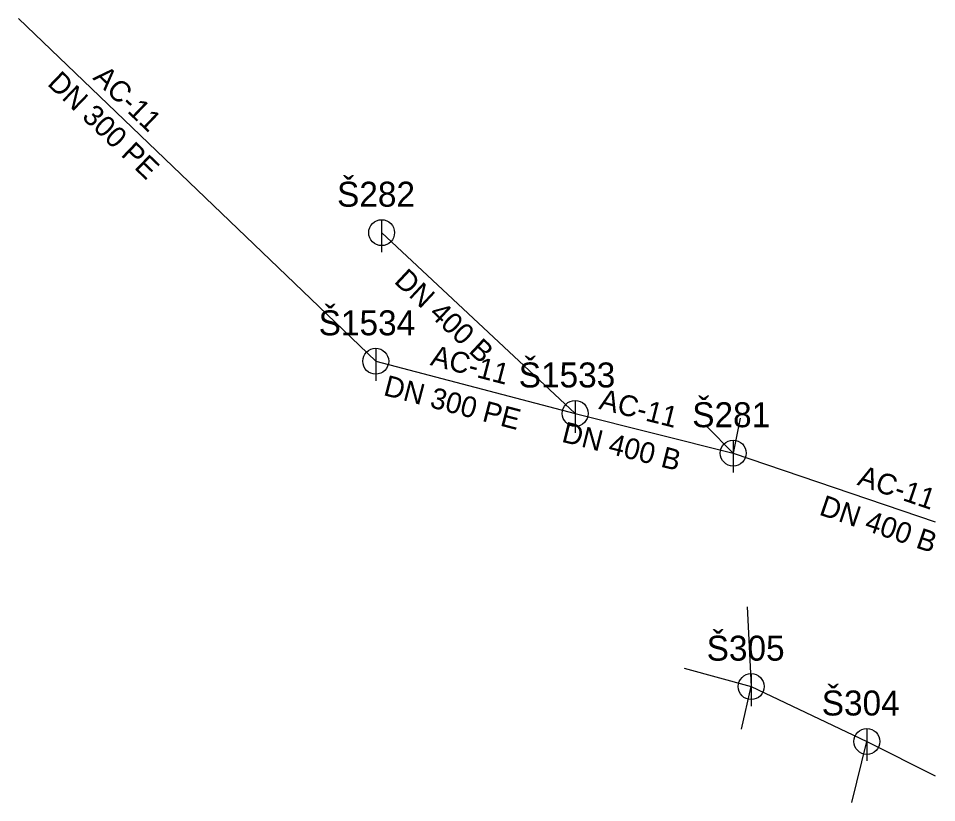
# Model space of a CAD drawing. Extents: x -483170.7 to -483099.9, y -1125989.9 to -1125929.4.
import ezdxf

# ---------------------------------------------------------------- set-up
doc = ezdxf.new("R2010")
doc.units = 0
for name, color, linetype in [('_pripojka_kanal_jednotna_priblizne_', 7, 'Continuous'), ('_stoka_destova_smvak_priblizne_', 7, 'Continuous'), ('_stoka_jednotna_provozovana_prevzato_z_dokumentace_', 7, 'Continuous'), ('_stoka_jednotna_smvak_prevzato_z_dokumentace_', 7, 'Continuous'), ('_stoka_jednotna_smvak_priblizne_', 7, 'Continuous'), ('Default', 7, 'Continuous'), ('MoLevel 1', 7, 'Continuous'), ('MoLevel 119', 7, 'Continuous'), ('MoLevel 120', 7, 'Continuous'), ('MoLevel 2', 7, 'Continuous'), ('MoLevel 5', 7, 'Continuous'), ('MoLevel 68', 7, 'Continuous'), ('MoLevel 69', 7, 'Continuous'), ('MoLevel 76', 7, 'Continuous'), ('MoLevel 77', 7, 'Continuous')]:
    doc.layers.add(name, color=color, linetype=linetype)

# ---------------------------------------------------------------- blocks, each defined once
blk = doc.blocks.new('_sachta_kanal_prevzato_z_dokumentace_')
at = {"layer": 'Default'}
blk.add_line((0, 0.00005), (0, -0.000075), dxfattribs=at)
blk.add_circle((0, 0), 0.00005, dxfattribs=at)

msp = doc.modelspace()

# ---------------------------------------------------------------- linework, layer by layer
at = {"layer": '_pripojka_kanal_jednotna_priblizne_'}
for p, q in [((-483115.054, -1125960.211), (-483115.589, -1125962.904)), ((-483117.628, -1125960.851), (-483115.589, -1125962.904)), ((-483114.512, -1125974.766), (-483114.201, -1125980.907)), ((-483119.377, -1125979.487), (-483114.201, -1125980.907)), ((-483114.964, -1125984.187), (-483114.201, -1125980.907)), ((-483106.447, -1125989.854), (-483105.277, -1125985.136))]:
    msp.add_line(p, q, dxfattribs=at)
at = {"layer": '_stoka_destova_smvak_priblizne_'}
msp.add_line((-483142.714, -1125945.9), (-483127.78, -1125959.84), dxfattribs=at)
at = {"layer": '_stoka_jednotna_provozovana_prevzato_z_dokumentace_'}
for p, q in [((-483170.738, -1125929.379), (-483143.17, -1125955.82)), ((-483143.17, -1125955.82), (-483127.78, -1125959.84))]:
    msp.add_line(p, q, dxfattribs=at)
at = {"layer": '_stoka_jednotna_smvak_prevzato_z_dokumentace_'}
for p, q in [((-483115.589, -1125962.905), (-483100.011, -1125968.201)), ((-483114.201, -1125980.907), (-483105.277, -1125985.136)), ((-483105.277, -1125985.136), (-483100.011, -1125987.776))]:
    msp.add_line(p, q, dxfattribs=at)
at = {"layer": '_stoka_jednotna_smvak_priblizne_'}
msp.add_line((-483127.78, -1125959.84), (-483115.589, -1125962.905), dxfattribs=at)

# ---------------------------------------------------------------- block references
at = {"layer": 'MoLevel 119', "xscale": 20000, "yscale": 20000}
for p in [(-483142.714, -1125945.901), (-483143.17, -1125955.82), (-483127.78, -1125959.84), (-483115.589, -1125962.905), (-483114.201, -1125980.907), (-483105.277, -1125985.136)]:
    msp.add_blockref('_sachta_kanal_prevzato_z_dokumentace_', p, dxfattribs=at)

# ---------------------------------------------------------------- texts
at = {"layer": 'MoLevel 1'}
msp.add_text('DN 400 B', height=1.6049, rotation=345.88579, dxfattribs=at).set_placement((-483128.895, -1125962.015))
at = {"layer": 'MoLevel 120'}
for s, p in [('Š282', (-483146.153, -1125943.901)), ('Š1534', (-483147.572, -1125953.82)), ('Š1533', (-483132.136, -1125957.84)), ('Š281', (-483118.753, -1125960.905)), ('Š305', (-483117.64, -1125978.907)), ('Š304', (-483108.762, -1125983.136))]:
    msp.add_text(s, height=1.9259, dxfattribs=at).set_placement(p)
at = {"layer": 'MoLevel 2'}
msp.add_text('AC-11', height=1.6049, rotation=345.88579, dxfattribs=at).set_placement((-483126.02, -1125959.483))
at = {"layer": 'MoLevel 5'}
msp.add_text('DN 400 B', height=1.6049, rotation=316.97246, dxfattribs=at).set_placement((-483141.829, -1125949.722))
at = {"layer": 'MoLevel 68'}
msp.add_text('DN 400 B', height=1.6049, rotation=341.22506, dxfattribs=at).set_placement((-483109.036, -1125967.628))
at = {"layer": 'MoLevel 69'}
msp.add_text('AC-11', height=1.6049, rotation=341.22506, dxfattribs=at).set_placement((-483106.095, -1125965.332))
at = {"layer": 'MoLevel 76'}
for rotation, p in [(316.19522, (-483168.575, -1125934.478)), (345.36095, (-483142.647, -1125958.416))]:
    msp.add_text('DN 300 PE', height=1.6049, rotation=rotation, dxfattribs=at).set_placement(p)
at = {"layer": 'MoLevel 77'}
for rotation, p in [(316.19522, (-483165.064, -1125934.021)), (345.36095, (-483139.024, -1125956.103))]:
    msp.add_text('AC-11', height=1.6049, rotation=rotation, dxfattribs=at).set_placement(p)

doc.saveas('drawing.dxf')
